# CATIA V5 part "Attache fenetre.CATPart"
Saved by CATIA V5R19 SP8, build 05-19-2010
Part number: Attache fenetre
Revision: ANY
Definition: UNKNOWN
Nomenclature: Attache fenetre
Source: Unknown
Bounding box of the stored display mesh (mm): x -19 to 19, y -18.5 to 18.5, z 0 to 15
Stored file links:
  D:\Documents\1_Travail\1 - ac-limoges.fr\OneDrive - ac-limoges.fr\STI2D_Turgot\2 -2I2D\3_SEQUENCE_Serre_Connectée\3- Spécificités\ITEC\EC 3 Ouverture automatique\Simulation  Ouverture Automatique\Attache fenetre.CATPart
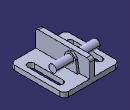
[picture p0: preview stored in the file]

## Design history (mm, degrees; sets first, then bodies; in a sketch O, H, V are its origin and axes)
Body1 "NONE" (main body)
  Solid1: solid without history
  Sketch1 on yz-plane, origin (0, 0, 0), H (0, 1, 0), V (0, 0, 1)
    circle A1 centre (6.5, 10.3) radius 2.6
    reference projected arc E1 centre (6.5, 10.3) radius 2.6 from (6.5, 7.7) to (6.5, 12.9) ccw from edge [face of Solid1 | face of Solid1]
    coincidence: A1 E1
  Pad1: profile Sketch1, direction (1, 0, 0), length 15, mirrored extent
